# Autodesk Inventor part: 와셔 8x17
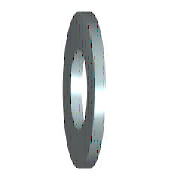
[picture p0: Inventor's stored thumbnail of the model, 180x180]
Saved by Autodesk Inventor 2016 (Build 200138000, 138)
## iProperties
Created: 2012-02
Part Number: 와셔 8x17
Material: 강철, 연강
Description: 평면 와셔
Document SubType Name: Modeling
Standard: KS B 1326
Designer: mduedu
Standards Organization: KS
Language: ko-KR
Size Designation: 8x17
Categories: <MemberInstance><Categories><Category DisplayName="조임쇠" InternalName="e4da775c-781d-43d5-af7c-5136215cf5a6" Mnemonic="FSTN"><Category DisplayName="와셔" InternalN
Density: 7.85 g/cm^3
Appearance: 파란색 - 벽 페인트 - 광택
Mass: 2.05184 g
Surface Area: 4.57416 cm^2
Volume: 0.261381 cm^3
IsCustomPart: 1
Author: mduedu
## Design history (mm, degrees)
sketch "스케치"
  geometry: C1 r 8.5 at (0, 0); C2 r 4.5 at (0, 0); 1 further point
  constraints: 2 centre point, 2 coincident
  dimensions: "d0" = 9 diameter of C2 (= SD1); "d1" = 17 diameter of C1 (= SD2)
extrude "본체" new body sketch "스케치" distance "d2" = 1.6 (= SD); taper "d3" = 0 deg
workaxis "Work Axis1"
workplane "Work Plane1"
body "Solid1"
other parameters: "SD1" = 9 [user parameter; used in 1 equation term], "SD2" = 17 [user parameter; used in 1 equation term], "SD" = 1.6 [user parameter; used in 1 equation term], "d4" = 0, "d5" = 0, "d6" = 0, "d7" = 0, "NND" = 8 [user parameter]
